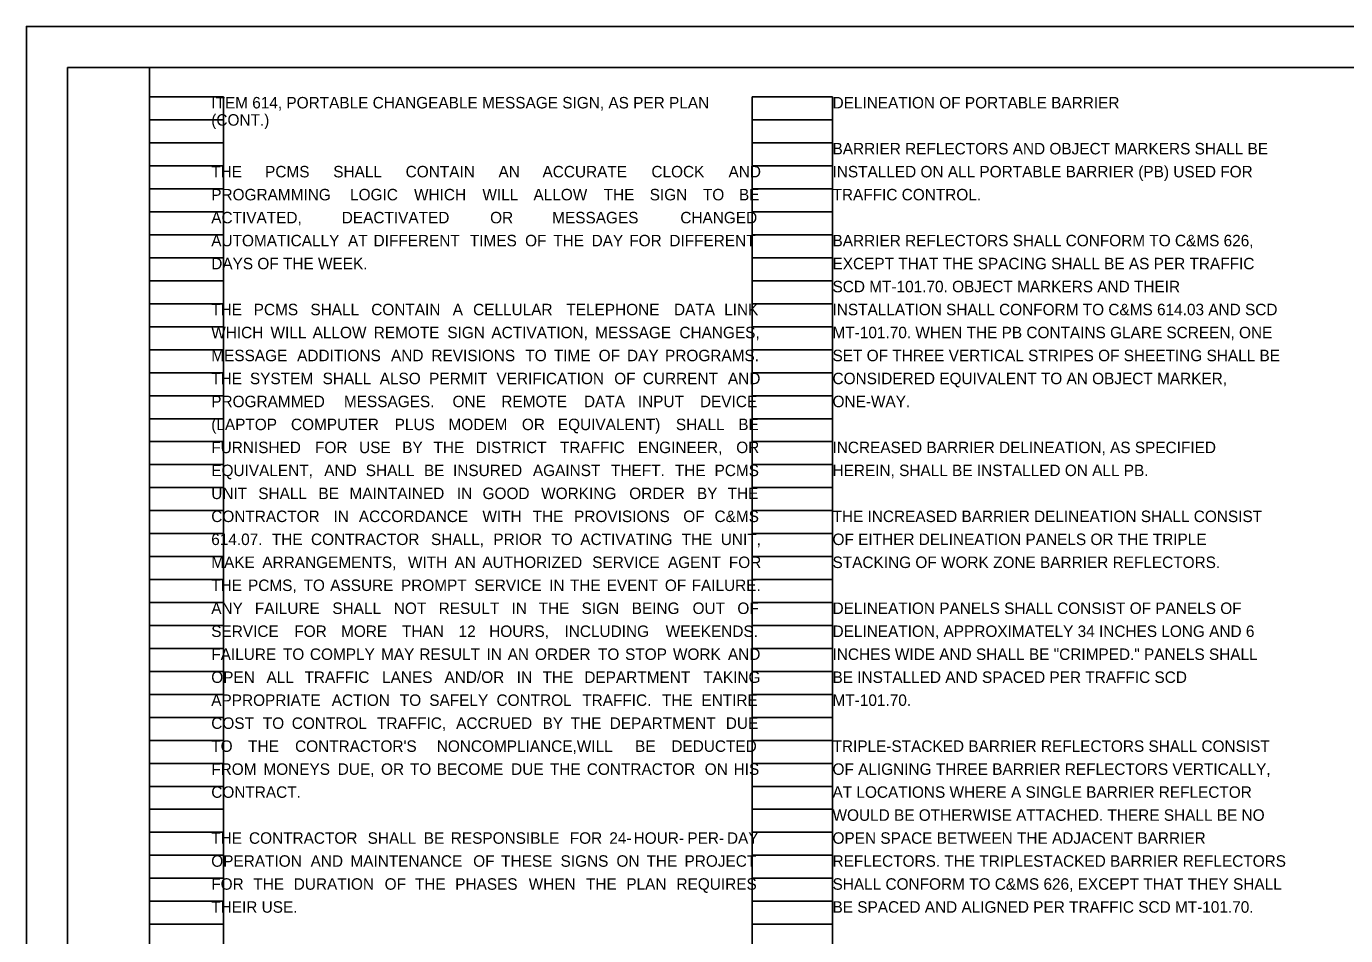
# Model space of a CAD drawing. Extents: x 0 to 34, y 0 to 22.
# Drawn here: x 0 to 16.07, y 10.92 to 22 of the extents above; entities that cross this region are included whole.
import ezdxf

# ---------------------------------------------------------------- set-up
doc = ezdxf.new("R2010")
doc.units = 0
for name, color, linetype in [('SH_Border', 7, 'Continuous'), ('SH_Cut_Line', 7, 'Continuous'), ('SH_Data', 7, 'Continuous'), ('SH_Text', 7, 'Continuous')]:
    doc.layers.add(name, color=color, linetype=linetype)

msp = doc.modelspace()

# ---------------------------------------------------------------- linework, layer by layer
at = {"layer": 'SH_Border'}
for points in [[(0.5, 21.5), (1.5, 21.5), (1.5, 0.5), (0.5, 0.5)], [(1.5, 21.5), (33.5, 21.5), (33.5, 0.5), (1.5, 0.5)]]:
    msp.add_lwpolyline(points, close=True, dxfattribs=at)
at = {"layer": 'SH_Cut_Line'}
msp.add_lwpolyline([(0, 0), (34, 0), (34, 22), (0, 22)], close=True, dxfattribs=at)
at = {"layer": 'SH_Data'}
for p, q in [((1.5, 0.98), (1.5, 21.14)), ((1.5, 21.14), (2.4, 21.14)), ((2.4, 0.98), (2.4, 21.14)), ((8.84, 0.98), (8.84, 21.14)), ((8.84, 21.14), (9.82, 21.14)), ((9.82, 0.98), (9.82, 21.14)), ((1.5, 20.86), (2.4, 20.86)), ((8.84, 20.86), (9.82, 20.86)), ((1.5, 20.58), (2.4, 20.58)), ((8.84, 20.58), (9.82, 20.58)), ((1.5, 20.3), (2.4, 20.3)), ((8.84, 20.3), (9.82, 20.3)), ((1.5, 20.02), (2.4, 20.02)), ((8.84, 20.02), (9.82, 20.02)), ((1.5, 19.74), (2.4, 19.74)), ((8.84, 19.74), (9.82, 19.74)), ((1.5, 19.46), (2.4, 19.46)), ((8.84, 19.46), (9.82, 19.46)), ((1.5, 19.18), (2.4, 19.18)), ((8.84, 19.18), (9.82, 19.18)), ((1.5, 18.9), (2.4, 18.9)), ((8.84, 18.9), (9.82, 18.9)), ((1.5, 18.62), (2.4, 18.62)), ((8.84, 18.62), (9.82, 18.62)), ((1.5, 18.34), (2.4, 18.34)), ((8.84, 18.34), (9.82, 18.34)), ((1.5, 18.06), (2.4, 18.06)), ((8.84, 18.06), (9.82, 18.06)), ((1.5, 17.78), (2.4, 17.78)), ((8.84, 17.78), (9.82, 17.78)), ((1.5, 17.5), (2.4, 17.5)), ((8.84, 17.5), (9.82, 17.5)), ((1.5, 17.22), (2.4, 17.22)), ((8.84, 17.22), (9.82, 17.22)), ((1.5, 16.94), (2.4, 16.94)), ((8.84, 16.94), (9.82, 16.94)), ((1.5, 16.66), (2.4, 16.66)), ((8.84, 16.66), (9.82, 16.66)), ((1.5, 16.38), (2.4, 16.38)), ((8.84, 16.38), (9.82, 16.38)), ((1.5, 16.1), (2.4, 16.1)), ((8.84, 16.1), (9.82, 16.1)), ((1.5, 15.82), (2.4, 15.82)), ((8.84, 15.82), (9.82, 15.82)), ((1.5, 15.54), (2.4, 15.54)), ((8.84, 15.54), (9.82, 15.54)), ((1.5, 15.26), (2.4, 15.26)), ((8.84, 15.26), (9.82, 15.26)), ((1.5, 14.98), (2.4, 14.98)), ((8.84, 14.98), (9.82, 14.98)), ((1.5, 14.7), (2.4, 14.7)), ((8.84, 14.7), (9.82, 14.7)), ((1.5, 14.42), (2.4, 14.42)), ((8.84, 14.42), (9.82, 14.42)), ((1.5, 14.14), (2.4, 14.14)), ((8.84, 14.14), (9.82, 14.14)), ((1.5, 13.86), (2.4, 13.86)), ((8.84, 13.86), (9.82, 13.86)), ((1.5, 13.58), (2.4, 13.58)), ((8.84, 13.58), (9.82, 13.58)), ((1.5, 13.3), (2.4, 13.3)), ((8.84, 13.3), (9.82, 13.3)), ((1.5, 13.02), (2.4, 13.02)), ((8.84, 13.02), (9.82, 13.02)), ((1.5, 12.74), (2.4, 12.74)), ((8.84, 12.74), (9.82, 12.74)), ((1.5, 12.46), (2.4, 12.46)), ((8.84, 12.46), (9.82, 12.46)), ((1.5, 12.18), (2.4, 12.18)), ((8.84, 12.18), (9.82, 12.18)), ((1.5, 11.9), (2.4, 11.9)), ((8.84, 11.9), (9.82, 11.9)), ((1.5, 11.62), (2.4, 11.62)), ((8.84, 11.62), (9.82, 11.62)), ((1.5, 11.34), (2.4, 11.34)), ((8.84, 11.34), (9.82, 11.34)), ((1.5, 11.06), (2.4, 11.06)), ((8.84, 11.06), (9.82, 11.06))]:
    msp.add_line(p, q, dxfattribs=at)

# ---------------------------------------------------------------- texts
at = {"layer": 'SH_Text'}
for s, p in [('ITEM 614, PORTABLE CHANGEABLE MESSAGE SIGN, AS PER PLAN ', (2.252, 21)), ('DELINEATION OF PORTABLE BARRIER', (9.82, 21)), ('(CONT.)', (2.252, 20.79)), ('BARRIER REFLECTORS AND OBJECT MARKERS SHALL BE', (9.82, 20.44)), ('THE ', (2.252, 20.16)), ('PCMS ', (2.908, 20.16)), ('SHALL ', (3.738, 20.16)), ('CONTAIN ', (4.62, 20.16)), ('AN ', (5.751, 20.16)), ('ACCURATE ', (6.287, 20.16)), ('CLOCK ', (7.614, 20.16)), ('AND ', (8.553, 20.16)), ('INSTALLED ON ALL PORTABLE BARRIER (PB) USED FOR', (9.82, 20.16)), ('PROGRAMMING ', (2.252, 19.88)), ('LOGIC ', (3.943, 19.88)), ('WHICH ', (4.722, 19.88)), ('WILL ', (5.555, 19.88)), ('ALLOW ', (6.177, 19.88)), ('THE ', (7.032, 19.88)), ('SIGN ', (7.593, 19.88)), ('TO ', (8.241, 19.88)), ('BE ', (8.68, 19.88)), ('TRAFFIC CONTROL.', (9.82, 19.88)), ('ACTIVATED, ', (2.252, 19.6)), ('DEACTIVATED ', (3.842, 19.6)), ('OR ', (5.649, 19.6)), ('MESSAGES ', (6.405, 19.6)), ('CHANGED ', (7.966, 19.6)), ('AUTOMATICALLY ', (2.252, 19.32)), ('AT ', (3.918, 19.32)), ('DIFFERENT ', (4.229, 19.32)), ('TIMES ', (5.402, 19.32)), ('OF ', (6.075, 19.32)), ('THE ', (6.418, 19.32)), ('DAY ', (6.885, 19.32)), ('FOR ', (7.344, 19.32)), ('DIFFERENT ', (7.832, 19.32)), ('BARRIER REFLECTORS SHALL CONFORM TO C&MS 626,', (9.82, 19.32)), ('DAYS OF THE WEEK.', (2.252, 19.04)), ('EXCEPT THAT THE SPACING SHALL BE AS PER TRAFFIC', (9.82, 19.04)), ('SCD MT-101.70. OBJECT MARKERS AND THEIR', (9.82, 18.76)), ('THE ', (2.252, 18.48)), ('PCMS ', (2.769, 18.48)), ('SHALL ', (3.46, 18.48)), ('CONTAIN ', (4.201, 18.48)), ('A ', (5.193, 18.48)), ('CELLULAR ', (5.442, 18.48)), ('TELEPHONE ', (6.578, 18.48)), ('DATA ', (7.889, 18.48)), ('LINK ', (8.5, 18.48)), ('INSTALLATION SHALL CONFORM TO C&MS 614.03 AND SCD', (9.82, 18.48)), ('WHICH ', (2.252, 18.2)), ('WILL ', (2.974, 18.2)), ('ALLOW ', (3.487, 18.2)), ('REMOTE ', (4.231, 18.2)), ('SIGN ', (5.128, 18.2)), ('ACTIVATION, ', (5.665, 18.2)), ('MESSAGE ', (6.928, 18.2)), ('CHANGES, ', (7.955, 18.2)), ('MT-101.70. WHEN THE PB CONTAINS GLARE SCREEN, ONE', (9.82, 18.2)), ('MESSAGE ', (2.252, 17.92)), ('ADDITIONS ', (3.298, 17.92)), ('AND ', (4.442, 17.92)), ('REVISIONS ', (4.934, 17.92)), ('TO ', (6.078, 17.92)), ('TIME ', (6.425, 17.92)), ('OF ', (6.971, 17.92)), ('DAY ', (7.317, 17.92)), ('PROGRAMS. ', (7.78, 17.92)), ('SET OF THREE VERTICAL STRIPES OF SHEETING SHALL BE', (9.82, 17.92)), ('THE ', (2.252, 17.64)), ('SYSTEM ', (2.723, 17.64)), ('SHALL ', (3.608, 17.64)), ('ALSO ', (4.304, 17.64)), ('PERMIT ', (4.906, 17.64)), ('VERIFICATION ', (5.726, 17.64)), ('OF ', (7.161, 17.64)), ('CURRENT ', (7.509, 17.64)), ('AND ', (8.546, 17.64)), ('CONSIDERED EQUIVALENT TO AN OBJECT MARKER,', (9.82, 17.64)), ('PROGRAMMED ', (2.252, 17.36)), ('MESSAGES. ', (3.868, 17.36)), ('ONE ', (5.191, 17.36)), ('REMOTE ', (5.785, 17.36)), ('DATA ', (6.792, 17.36)), ('INPUT ', (7.448, 17.36)), ('DEVICE ', (8.205, 17.36)), ('ONE-WAY.', (9.82, 17.36)), ('(LAPTOP ', (2.252, 17.08)), ('COMPUTER ', (3.223, 17.08)), ('PLUS ', (4.486, 17.08)), ('MODEM ', (5.142, 17.08)), ('OR ', (6.036, 17.08)), ('EQUIVALENT) ', (6.474, 17.08)), ('SHALL ', (7.912, 17.08)), ('BE ', (8.672, 17.08)), ('FURNISHED ', (2.252, 16.8)), ('FOR ', (3.516, 16.8)), ('USE ', (4.053, 16.8)), ('BY ', (4.578, 16.8)), ('THE ', (4.959, 16.8)), ('DISTRICT ', (5.473, 16.8)), ('TRAFFIC ', (6.499, 16.8)), ('ENGINEER, ', (7.448, 16.8)), ('OR ', (8.647, 16.8)), ('INCREASED BARRIER DELINEATION, AS SPECIFIED', (9.82, 16.8)), ('EQUIVALENT, ', (2.252, 16.52)), ('AND ', (3.628, 16.52)), ('SHALL ', (4.134, 16.52)), ('BE ', (4.843, 16.52)), ('INSURED ', (5.197, 16.52)), ('AGAINST ', (6.17, 16.52)), ('THEFT. ', (7.122, 16.52)), ('THE ', (7.899, 16.52)), ('PCMS ', (8.383, 16.52)), ('HEREIN, SHALL BE INSTALLED ON ALL PB.', (9.82, 16.52)), ('UNIT ', (2.252, 16.24)), ('SHALL ', (2.825, 16.24)), ('BE ', (3.558, 16.24)), ('MAINTAINED ', (3.936, 16.24)), ('IN ', (5.245, 16.24)), ('GOOD ', (5.557, 16.24)), ('WORKING ', (6.271, 16.24)), ('ORDER ', (7.344, 16.24)), ('BY ', (8.168, 16.24)), ('THE ', (8.542, 16.24)), ('CONTRACTOR ', (2.252, 15.96)), ('IN ', (3.742, 15.96)), ('ACCORDANCE ', (4.05, 15.96)), ('WITH ', (5.555, 15.96)), ('THE ', (6.167, 15.96)), ('PROVISIONS ', (6.672, 15.96)), ('OF ', (8.002, 15.96)), ('C&MS ', (8.383, 15.96)), ('THE INCREASED BARRIER DELINEATION SHALL CONSIST', (9.82, 15.96)), ('614.07. ', (2.252, 15.68)), ('THE ', (2.99, 15.68)), ('CONTRACTOR ', (3.467, 15.68)), ('SHALL, ', (4.929, 15.68)), ('PRIOR ', (5.689, 15.68)), ('TO ', (6.394, 15.68)), ('ACTIVATING ', (6.748, 15.68)), ('THE ', (7.982, 15.68)), ('UNIT, ', (8.459, 15.68)), ('OF EITHER DELINEATION PANELS OR THE TRIPLE', (9.82, 15.68)), ('MAKE ', (2.252, 15.4)), ('ARRANGEMENTS, ', (2.874, 15.4)), ('WITH ', (4.648, 15.4)), ('AN ', (5.215, 15.4)), ('AUTHORIZED ', (5.554, 15.4)), ('SERVICE ', (6.893, 15.4)), ('AGENT ', (7.815, 15.4)), ('FOR ', (8.557, 15.4)), ('STACKING OF WORK ZONE BARRIER REFLECTORS.', (9.82, 15.4)), ('THE ', (2.252, 15.12)), ('PCMS, ', (2.7, 15.12)), ('TO ', (3.376, 15.12)), ('ASSURE ', (3.701, 15.12)), ('PROMPT ', (4.563, 15.12)), ('SERVICE ', (5.456, 15.12)), ('IN ', (6.368, 15.12)), ('THE ', (6.621, 15.12)), ('EVENT ', (7.069, 15.12)), ('OF ', (7.778, 15.12)), ('FAILURE. ', (8.103, 15.12)), ('ANY ', (2.252, 14.84)), ('FAILURE ', (2.783, 14.84)), ('SHALL ', (3.727, 14.84)), ('NOT ', (4.476, 14.84)), ('RESULT ', (5.022, 14.84)), ('IN ', (5.911, 14.84)), ('THE ', (6.24, 14.84)), ('SIGN ', (6.763, 14.84)), ('BEING ', (7.374, 14.84)), ('OUT ', (8.115, 14.84)), ('OF ', (8.661, 14.84)), ('DELINEATION PANELS SHALL CONSIST OF PANELS OF', (9.82, 14.84)), ('SERVICE ', (2.252, 14.56)), ('FOR ', (3.264, 14.56)), ('MORE ', (3.833, 14.56)), ('THAN ', (4.576, 14.56)), ('12 ', (5.265, 14.56)), ('HOURS, ', (5.638, 14.56)), ('INCLUDING ', (6.555, 14.56)), ('WEEKENDS. ', (7.788, 14.56)), ('DELINEATION, APPROXIMATELY 34 INCHES LONG AND 6', (9.82, 14.56)), ('FAILURE ', (2.252, 14.28)), ('TO ', (3.125, 14.28)), ('COMPLY ', (3.454, 14.28)), ('MAY ', (4.32, 14.28)), ('RESULT ', (4.787, 14.28)), ('IN ', (5.606, 14.28)), ('AN ', (5.863, 14.28)), ('ORDER ', (6.196, 14.28)), ('TO ', (6.963, 14.28)), ('STOP ', (7.293, 14.28)), ('WORK ', (7.876, 14.28)), ('AND ', (8.546, 14.28)), ('INCHES WIDE AND SHALL BE "CRIMPED." PANELS SHALL', (9.82, 14.28)), ('OPEN ', (2.252, 14)), ('TRAFFIC ', (3.388, 14)), ('LANES ', (4.333, 14)), ('AND/OR ', (5.093, 14)), ('TAKING ', (8.245, 14)), ('BE INSTALLED AND SPACED PER TRAFFIC SCD', (9.82, 14)), ('ALL ', (2.925, 14)), ('IN ', (5.973, 14)), ('THE ', (6.287, 14)), ('DEPARTMENT ', (6.797, 14)), ('APPROPRIATE ', (2.252, 13.72)), ('ACTION ', (3.72, 13.72)), ('TO ', (4.549, 13.72)), ('SAFELY ', (4.908, 13.72)), ('CONTROL ', (5.727, 13.72)), ('TRAFFIC. ', (6.771, 13.72)), ('THE ', (7.741, 13.72)), ('ENTIRE ', (8.223, 13.72)), ('MT-101.70.', (9.82, 13.72)), ('COST ', (2.252, 13.44)), ('TO ', (2.88, 13.44)), ('CONTROL ', (3.233, 13.44)), ('TRAFFIC, ', (4.271, 13.44)), ('ACCRUED ', (5.235, 13.44)), ('BY ', (6.288, 13.44)), ('THE ', (6.63, 13.44)), ('DEPARTMENT ', (7.106, 13.44)), ('DUE ', (8.52, 13.44)), ('TO ', (2.252, 13.16)), ('THE ', (2.701, 13.16)), ("CONTRACTOR'S ", (3.273, 13.16)), ('NONCOMPLIANCE,WILL ', (4.999, 13.16)), ('BE ', (7.415, 13.16)), ('DEDUCTED ', (7.857, 13.16)), ('TRIPLE-STACKED BARRIER REFLECTORS SHALL CONSIST', (9.82, 13.16)), ('FROM ', (2.252, 12.88)), ('MONEYS ', (2.887, 12.88)), ('DUE, ', (3.793, 12.88)), ('OR ', (4.32, 12.88)), ('TO ', (4.672, 12.88)), ('BECOME ', (4.999, 12.88)), ('DUE ', (5.905, 12.88)), ('THE ', (6.377, 12.88)), ('CONTRACTOR ', (6.827, 12.88)), ('ON ', (8.263, 12.88)), ('HIS ', (8.615, 12.88)), ('OF ALIGNING THREE BARRIER REFLECTORS VERTICALLY,', (9.82, 12.88)), ('CONTRACT.', (2.252, 12.6)), ('AT LOCATIONS WHERE A SINGLE BARRIER REFLECTOR', (9.82, 12.6)), ('WOULD BE OTHERWISE ATTACHED. THERE SHALL BE NO', (9.82, 12.32)), ('THE ', (2.252, 12.04)), ('CONTRACTOR ', (2.712, 12.04)), ('SHALL ', (4.157, 12.04)), ('BE ', (4.841, 12.04)), ('RESPONSIBLE ', (5.17, 12.04)), ('FOR ', (6.619, 12.04)), ('24-', (7.101, 12.04)), ('HOUR-', (7.397, 12.04)), ('PER-', (8.052, 12.04)), ('DAY ', (8.534, 12.04)), ('OPEN SPACE BETWEEN THE ADJACENT BARRIER', (9.82, 12.04)), ('OPERATION ', (2.252, 11.76)), ('AND ', (3.462, 11.76)), ('MAINTENANCE ', (3.947, 11.76)), ('OF ', (5.443, 11.76)), ('THESE ', (5.783, 11.76)), ('SIGNS ', (6.507, 11.76)), ('ON ', (7.188, 11.76)), ('THE ', (7.554, 11.76)), ('PROJECT ', (8.017, 11.76)), ('REFLECTORS. THE TRIPLESTACKED BARRIER REFLECTORS', (9.82, 11.76)), ('FOR ', (2.252, 11.48)), ('THE ', (2.765, 11.48)), ('DURATION ', (3.257, 11.48)), ('OF ', (4.364, 11.48)), ('THE ', (4.733, 11.48)), ('PHASES ', (5.224, 11.48)), ('WHEN ', (6.119, 11.48)), ('THE ', (6.817, 11.48)), ('PLAN ', (7.308, 11.48)), ('REQUIRES ', (7.919, 11.48)), ('SHALL CONFORM TO C&MS 626, EXCEPT THAT THEY SHALL', (9.82, 11.48)), ('THEIR USE.', (2.252, 11.2)), ('BE SPACED AND ALIGNED PER TRAFFIC SCD MT-101.70.', (9.82, 11.2))]:
    msp.add_text(s, height=0.14, dxfattribs=at).set_placement(p)

doc.saveas('drawing.dxf')
